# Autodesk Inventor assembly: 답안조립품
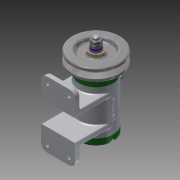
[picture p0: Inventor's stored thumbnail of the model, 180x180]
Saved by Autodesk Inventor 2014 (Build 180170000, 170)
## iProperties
Created: 2017-02
Part Number: 답안조립품
Document SubType Name: Assembly
Designer: 601-
Author: 601-
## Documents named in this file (16)
- C:\Users\601-\Desktop\470208V1019\답안조립품.iam
- C:\Users\601-\Desktop\470208V1019\본체.ipt
- C:\Users\601-\Desktop\470208V1019\뒤커버.ipt
- C:\Users\601-\Desktop\470208V1019\앞커버.ipt
- C:\Users\601-\Desktop\470208V1019\베어링 15 x 32 x 9.ipt
- C:\Users\601-\Desktop\470208V1019\축.ipt
- C:\Users\601-\Desktop\470208V1019\V벨트풀리.ipt
- C:\Users\601-\Desktop\470208V1019\키 3 x 3 x 12.ipt
- C:\Users\601-\Desktop\470208V1019\와셔 8x17.ipt
- C:\Users\601-\Desktop\470208V1019\스프링와셔 8.ipt
- C:\Users\601-\Desktop\470208V1019\너트 M 8.ipt
- C:\Users\601-\Desktop\470208V1019\니플 M 6 x 0.75.ipt
- C:\Users\601-\Desktop\470208V1019\볼트 M 6 x 8.ipt
- C:\Users\601-\Desktop\470208V1019\와셔 6x11.5.ipt
- C:\Users\601-\Desktop\470208V1019\볼트 M4 x 12.ipt
- C:\Users\601-\Desktop\470208V1019\오일 실 15 25 7.ipt
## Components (11 placed, 3 different names)
1. KS B 2023 6002 - 15 x 32 x 9:1
2. KS B 2023 6002 - 15 x 32 x 9:2
3. V벨트풀리:1 — 각도:2
4. ISO 4762 M4 x 12:2
5. ISO 4762 M4 x 12:3
6. ISO 4762 M4 x 12:4
7. ISO 4762 M4 x 12:5
8. ISO 4762 M4 x 12:1
9. ISO 4762 M4 x 12:6
10. ISO 4762 M4 x 12:7
11. ISO 4762 M4 x 12:8
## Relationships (1: Angle 1)
- 각도:2 [Angle]: V벨트풀리:1
